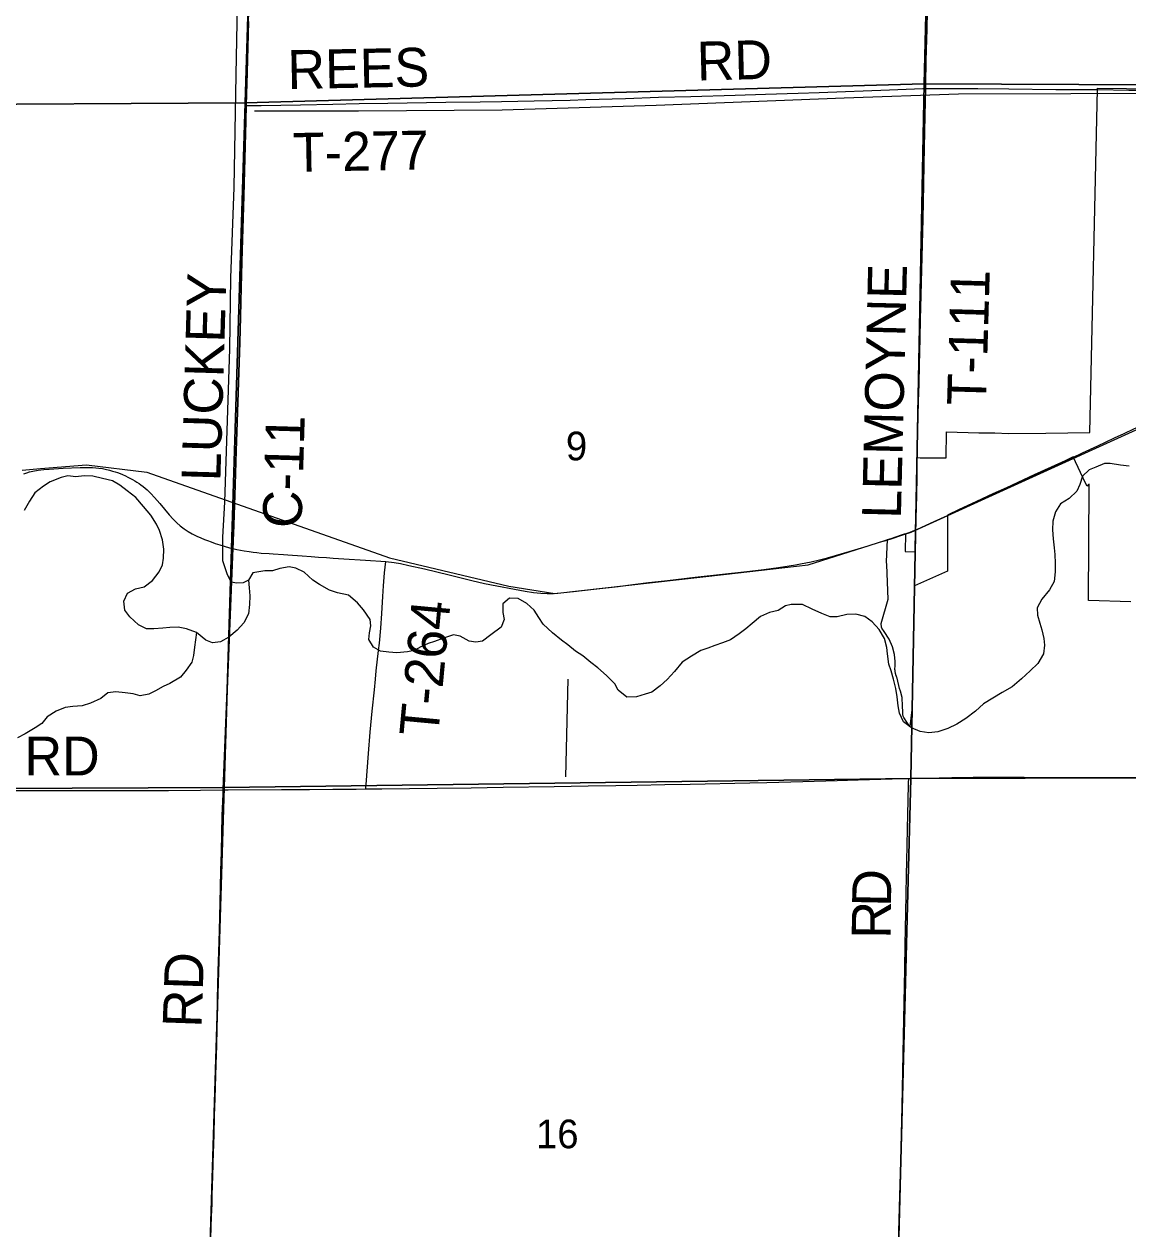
# Model space of a CAD drawing. Extents: x -8.3 to 42.1, y 0 to 22.
# Drawn here: x 3.551 to 5.164, y 15.682 to 17.442 of the extents above; entities that cross this region are included whole.
import ezdxf

# ---------------------------------------------------------------- set-up
doc = ezdxf.new("R2010")
doc.units = 0
for name, color, linetype in [('GM_X_Corporation', 7, 'Continuous'), ('GM_X_County_Road', 7, 'Continuous'), ('GM_X_County_Road_Text', 7, 'Continuous'), ('GM_X_Major_River', 7, 'Continuous'), ('GM_X_Minor_River', 7, 'Continuous'), ('GM_X_Rail_Line', 7, 'Continuous'), ('GM_X_Section', 7, 'Continuous'), ('GM_X_Section_Text', 7, 'Continuous'), ('GM_X_State_Route', 7, 'Continuous'), ('GM_X_Township_Road', 7, 'Continuous'), ('GM_X_Township_Road_Text', 7, 'Continuous')]:
    doc.layers.add(name, color=color, linetype=linetype)

msp = doc.modelspace()

# ---------------------------------------------------------------- linework, layer by layer
at = {"layer": 'GM_X_Corporation'}
msp.add_lwpolyline([(5.168, 16.5978), (5.1062, 16.5996), (5.1071, 16.7676), (5.1071, 16.7697), (5.1065, 16.7694), (5.1063, 16.7691), (5.1056, 16.7685), (5.1047, 16.7672), (5.1043, 16.7669), (5.104, 16.7665), (5.1016, 16.7709), (5.0836, 16.8095), (5.0718, 16.8039), (5.0268, 16.7831), (4.986, 16.7642), (4.9662, 16.7553), (4.9423, 16.7441), (4.917, 16.7324), (4.8999, 16.7245), (4.8999, 16.6423), (4.8518, 16.6212), (4.8486, 16.4449), (4.8481, 16.4398), (4.8451, 16.4155), (4.8406, 16.4218), (4.836, 16.4288), (4.8353, 16.4306), (4.8348, 16.4332), (4.8347, 16.4357), (4.8345, 16.4469), (4.834, 16.4565), (4.8339, 16.4579), (4.8312, 16.4671), (4.8301, 16.4709), (4.8266, 16.4862), (4.8262, 16.487), (4.8254, 16.4888), (4.8247, 16.4909), (4.8245, 16.4917), (4.824, 16.4932), (4.8239, 16.4939), (4.8237, 16.4951), (4.8234, 16.4973), (4.8233, 16.4989), (4.8233, 16.5008), (4.8234, 16.5027), (4.8235, 16.5034), (4.8237, 16.5103), (4.8227, 16.5208), (4.8199, 16.5317), (4.815, 16.543), (4.8073, 16.5541), (4.8042, 16.559), (4.8034, 16.5607), (4.803, 16.5659), (4.8134, 16.6015), (4.8113, 16.6515), (4.8111, 16.656), (4.8125, 16.6887), (4.8175, 16.6904), (4.833, 16.6956), (4.8386, 16.6976), (4.8383, 16.6711), (4.8526, 16.6707), (4.8533, 16.7034), (4.8543, 16.7338), (4.8555, 16.7785), (4.8557, 16.8086), (4.8599, 16.8081), (4.8983, 16.8082), (4.8986, 16.8461), (4.9457, 16.8448), (4.9694, 16.8448), (4.9892, 16.8438), (5.0437, 16.8441), (5.1079, 16.8452), (5.1193, 17.3466), (5.1193, 17.3479), (5.2037, 17.3472)], dxfattribs=at)
at = {"layer": 'GM_X_County_Road'}
for points in [[(3.8757, 17.3226), (3.877, 17.3706), (3.879, 17.4452), (3.8806, 17.5011), (3.8816, 17.5384), (3.8831, 17.5849), (3.8856, 17.6719), (3.8863, 17.7061), (3.8879, 17.7527), (3.8907, 17.849), (3.8925, 17.908), (3.8942, 17.967), (3.8964, 18.0294), (3.8977, 18.0647), (3.9001, 18.1317), (3.9019, 18.1908), (3.9046, 18.2684), (3.9056, 18.2932), (3.9067, 18.3032), (3.9076, 18.314), (3.9079, 18.3179)], [(3.8562, 16.6754), (3.8567, 16.684), (3.8569, 16.6872), (3.8578, 16.7089), (3.8596, 16.7679), (3.861, 16.8176), (3.862, 16.8456), (3.8634, 16.8891), (3.8662, 16.976), (3.8674, 17.0133), (3.8684, 17.0568), (3.8694, 17.0941), (3.8722, 17.1904), (3.8751, 17.2991), (3.8757, 17.3226)]]:
    msp.add_lwpolyline(points, dxfattribs=at)
at = {"layer": 'GM_X_Major_River'}
for points in [[(5.1655, 16.7961), (5.1526, 16.7975), (5.1379, 16.8), (5.1296, 16.8), (5.1166, 16.7946), (5.107, 16.7906), (5.0973, 16.7814), (5.0932, 16.7693), (5.0892, 16.7596), (5.0776, 16.7485), (5.0649, 16.7408), (5.0578, 16.7292), (5.054, 16.7153), (5.0533, 16.7028), (5.0542, 16.6898), (5.0557, 16.6765), (5.0566, 16.667), (5.0571, 16.6541), (5.0575, 16.6415), (5.056, 16.6275), (5.0489, 16.6152), (5.0379, 16.6014), (5.0312, 16.589), (5.0317, 16.5784), (5.0348, 16.5666), (5.0376, 16.557), (5.0407, 16.544), (5.0416, 16.5345), (5.0401, 16.5217), (5.0318, 16.5074), (5.0206, 16.4967), (5.0082, 16.4852), (4.9946, 16.4734), (4.9797, 16.4654), (4.9527, 16.4486), (4.9411, 16.4379), (4.9268, 16.4272), (4.9138, 16.4192), (4.9007, 16.4127), (4.8858, 16.4077), (4.8729, 16.4062), (4.8601, 16.4084), (4.8474, 16.4136), (4.8358, 16.4222), (4.8297, 16.4349), (4.8281, 16.4459), (4.8265, 16.4589)], [(3.8621, 16.5562), (3.8501, 16.5459), (3.8378, 16.5394), (3.8261, 16.5377), (3.8163, 16.5418), (3.803, 16.5531), (3.7883, 16.5582), (3.7759, 16.5606), (3.7638, 16.5601), (3.7539, 16.5592), (3.7406, 16.5584), (3.73, 16.5583), (3.718, 16.5639), (3.7054, 16.5756), (3.6981, 16.5856), (3.6967, 16.5988), (3.7021, 16.6102), (3.714, 16.6167), (3.7262, 16.6195), (3.7386, 16.6287), (3.7483, 16.6413), (3.7531, 16.6515), (3.7549, 16.6613), (3.7552, 16.6746), (3.7533, 16.6883), (3.7487, 16.7017), (3.7444, 16.7113), (3.736, 16.7244), (3.7257, 16.7371), (3.7143, 16.7499), (3.7017, 16.7597), (3.6909, 16.7683), (3.6804, 16.7743), (3.6658, 16.7781), (3.6515, 16.7811), (3.639, 16.7817), (3.6268, 16.7805), (3.6151, 16.7816), (3.6052, 16.7795), (3.5891, 16.7731), (3.5795, 16.7669), (3.5668, 16.7569), (3.5589, 16.7446), (3.551, 16.7311)], [(4.8265, 16.4589), (4.8245, 16.4711), (4.8211, 16.4845), (4.8176, 16.4967), (4.8144, 16.5066), (4.8125, 16.5215), (4.8113, 16.531), (4.8078, 16.544), (4.8002, 16.5574), (4.7898, 16.5683), (4.7794, 16.5762), (4.7663, 16.5799), (4.753, 16.5791), (4.7389, 16.576), (4.7287, 16.5759), (4.7163, 16.5807), (4.7025, 16.5871), (4.6882, 16.5939), (4.6716, 16.5939), (4.6632, 16.5919), (4.6528, 16.5849), (4.6398, 16.5822), (4.6268, 16.5761), (4.6148, 16.5661), (4.6052, 16.558), (4.5955, 16.551), (4.5832, 16.5422), (4.5713, 16.5379), (4.5603, 16.534), (4.5499, 16.5301), (4.5396, 16.5266), (4.5258, 16.5182), (4.5123, 16.5094), (4.501, 16.496), (4.4905, 16.4841), (4.4804, 16.4752), (4.4681, 16.4657), (4.4585, 16.4629), (4.4455, 16.459), (4.4315, 16.4586), (4.4189, 16.4684), (4.4138, 16.478), (4.402, 16.49), (4.3894, 16.5013), (4.379, 16.5092), (4.3671, 16.519), (4.3567, 16.5257), (4.3456, 16.535), (4.3359, 16.5417), (4.3229, 16.5523), (4.3092, 16.5652), (4.303, 16.5748), (4.2961, 16.5856), (4.2857, 16.5953), (4.273, 16.6025), (4.2601, 16.6028), (4.2505, 16.595), (4.2505, 16.5821), (4.2522, 16.5718), (4.2481, 16.5606), (4.2327, 16.5495), (4.2207, 16.54), (4.2112, 16.5387), (4.2014, 16.5404), (4.1883, 16.5476), (4.1782, 16.5497), (4.1637, 16.5448), (4.1507, 16.5398), (4.1411, 16.537), (4.1308, 16.5319), (4.1208, 16.5268), (4.1109, 16.5248), (4.0957, 16.5233), (4.084, 16.5243), (4.0719, 16.5257), (4.0614, 16.5315), (4.0545, 16.5425), (4.0555, 16.5523), (4.0577, 16.5625), (4.0568, 16.572), (4.0469, 16.5859), (4.0381, 16.5964), (4.0251, 16.6073), (4.0089, 16.6107), (3.9974, 16.6149), (3.9827, 16.6228), (3.973, 16.6291), (3.96, 16.6412), (3.9481, 16.6468), (3.9383, 16.6489), (3.9246, 16.6462), (3.9139, 16.643), (3.9025, 16.6429), (3.885, 16.64), (3.8788, 16.6293), (3.8796, 16.618), (3.8808, 16.6066), (3.8801, 16.5937), (3.879, 16.5801), (3.8719, 16.567), (3.8621, 16.5562)]]:
    msp.add_lwpolyline(points, dxfattribs=at)
at = {"layer": 'GM_X_Minor_River'}
for points in [[(3.8788, 16.6293), (3.8711, 16.6256), (3.8618, 16.6248), (3.8536, 16.6266), (3.8475, 16.6386), (3.8412, 16.6577), (3.8413, 16.6922), (3.8444, 16.7434), (3.8481, 16.8625), (3.8518, 16.9671), (3.8529, 17.0711), (3.8581, 17.203), (3.861, 17.3677), (3.8634, 17.4951), (3.8685, 17.624), (3.8727, 17.7484), (3.8761, 17.8546), (3.8811, 18.0272), (3.8862, 18.1546), (3.8894, 18.2972)], [(3.8877, 17.315), (4.0396, 17.3152), (4.2494, 17.3165), (4.4745, 17.3232), (4.749, 17.334), (4.9161, 17.3399), (5.0801, 17.3405), (5.2547, 17.3408)], [(3.803, 16.5531), (3.7998, 16.5315), (3.7987, 16.5194), (3.7962, 16.5096), (3.788, 16.4977), (3.7794, 16.4876), (3.764, 16.4785), (3.7544, 16.4738), (3.7429, 16.4676), (3.7333, 16.4629), (3.7204, 16.4606), (3.7102, 16.4631), (3.6985, 16.4649), (3.6849, 16.466), (3.6735, 16.4648), (3.6631, 16.4563), (3.6482, 16.4498), (3.6359, 16.4456), (3.6223, 16.4448), (3.6109, 16.4435), (3.5979, 16.4378), (3.5848, 16.4297), (3.577, 16.42), (3.5674, 16.4134), (3.5528, 16.4047), (3.5413, 16.3989)], [(4.3455, 16.4846), (4.3419, 16.342)]]:
    msp.add_lwpolyline(points, dxfattribs=at)
at = {"layer": 'GM_X_Rail_Line'}
msp.add_lwpolyline([(3.5481, 16.7901), (3.5751, 16.7924), (3.642, 16.7979), (3.7302, 16.7871), (4.0849, 16.6622), (4.2594, 16.6204), (4.3265, 16.61), (4.5771, 16.6383), (4.6964, 16.6517), (4.847, 16.6995), (5.3428, 16.9248)], dxfattribs=at)
at = {"layer": 'GM_X_Section'}
for points in [[(2.9069, 18.3295), (2.9164, 18.3298), (3.9047, 18.3241), (3.8739, 17.3266), (2.8735, 17.321)], [(3.9115, 18.3241), (4.8893, 18.3249), (4.866, 17.3546), (3.8739, 17.3266), (3.9047, 18.3241)], [(4.9147, 18.3251), (5.8932, 18.3221), (5.8682, 17.3386), (5.431, 17.3522), (4.866, 17.3546), (4.8893, 18.3249)], [(4.866, 17.3546), (4.8464, 16.3395), (3.8435, 16.3264), (3.8739, 17.3266)], [(5.8682, 17.3386), (5.8503, 16.3424), (4.8464, 16.3395), (4.866, 17.3546), (5.431, 17.3522)], [(3.8739, 17.3266), (3.8435, 16.3264), (2.8424, 16.322), (2.8735, 17.321)], [(3.8435, 16.3264), (4.8464, 16.3395), (4.8204, 15.3344), (3.8127, 15.327)], [(4.8464, 16.3395), (5.8503, 16.3424), (5.8197, 15.3608), (4.8204, 15.3344)], [(3.8435, 16.3264), (3.8127, 15.327), (2.8124, 15.3208), (2.8424, 16.322)]]:
    msp.add_lwpolyline(points, close=True, dxfattribs=at)
at = {"layer": 'GM_X_State_Route'}
msp.add_line((5.0839, 16.809), (5.0953, 16.8145), dxfattribs=at)
for points in [[(5.1589, 16.8442), (5.1715, 16.8501), (5.1828, 16.8552), (5.2025, 16.8642), (5.2209, 16.8722), (5.2228, 16.873), (5.2326, 16.8773), (5.2531, 16.8864), (5.2686, 16.8933), (5.2769, 16.8974), (5.284, 16.9005), (5.2872, 16.902), (5.2956, 16.9059), (5.3006, 16.908), (5.3091, 16.9116), (5.3176, 16.9154), (5.3316, 16.9218), (5.3356, 16.9237), (5.3499, 16.9301), (5.3519, 16.931)], [(5.0953, 16.8145), (5.0971, 16.8154), (5.1197, 16.8258), (5.1438, 16.8372), (5.158, 16.8438), (5.1589, 16.8442)], [(3.5507, 16.7847), (3.5552, 16.7863), (3.5591, 16.7874), (3.564, 16.7885), (3.5714, 16.7899), (3.5801, 16.7911), (3.5875, 16.7917), (3.608, 16.7928), (3.6329, 16.7937), (3.6429, 16.7939), (3.651, 16.7939), (3.6556, 16.7936), (3.6604, 16.7931), (3.6654, 16.7923), (3.6696, 16.7914), (3.6757, 16.7901), (3.6802, 16.7888), (3.6841, 16.7875), (3.6875, 16.7864), (3.6912, 16.785), (3.695, 16.7835), (3.6991, 16.7817), (3.7028, 16.7799), (3.7065, 16.778), (3.7096, 16.7763), (3.7126, 16.7746), (3.7158, 16.7726), (3.7189, 16.7705), (3.7218, 16.7684), (3.7249, 16.7661), (3.7278, 16.7638), (3.7307, 16.7612), (3.7361, 16.756), (3.7417, 16.7501), (3.7493, 16.7411), (3.763, 16.7249), (3.7688, 16.7185), (3.7718, 16.7155), (3.774, 16.7133), (3.779, 16.7088), (3.785, 16.7041), (3.7905, 16.7005), (3.7968, 16.6968), (3.8033, 16.6937), (3.8093, 16.691), (3.8146, 16.6888), (3.8192, 16.6871), (3.8241, 16.6853), (3.8303, 16.683), (3.8369, 16.6808), (3.8433, 16.6788), (3.8513, 16.6766), (3.8562, 16.6754)], [(4.9001, 16.724), (4.9172, 16.7319), (4.9426, 16.7435), (4.9664, 16.7548), (4.9862, 16.7636), (5.027, 16.7825), (5.072, 16.8034), (5.0839, 16.809)], [(4.8535, 16.7028), (4.8561, 16.7038), (4.8807, 16.7149), (4.8955, 16.7217), (4.9001, 16.724)], [(3.8562, 16.6754), (3.8616, 16.6742), (3.8671, 16.6731), (3.8725, 16.6721), (3.8799, 16.671), (3.8855, 16.6703), (3.8912, 16.6696), (3.8973, 16.669), (3.9089, 16.6681), (3.9151, 16.6676), (3.9299, 16.6666), (3.9361, 16.6662), (3.9572, 16.6647), (3.9704, 16.6638), (3.9809, 16.663), (3.9927, 16.6623), (4.0025, 16.6617), (4.018, 16.6606), (4.0496, 16.6587), (4.0794, 16.6564), (4.0915, 16.655), (4.1008, 16.6535), (4.113, 16.651), (4.1358, 16.6457), (4.1539, 16.6415), (4.1721, 16.6371), (4.2052, 16.6288), (4.2234, 16.6246), (4.2416, 16.6209), (4.2676, 16.616), (4.2829, 16.6133), (4.2952, 16.6115), (4.3059, 16.6103), (4.3152, 16.6099), (4.3245, 16.61), (4.3353, 16.6108), (4.3538, 16.6127), (4.3878, 16.6166), (4.4187, 16.6203), (4.4402, 16.623), (4.4634, 16.6259), (4.4912, 16.629), (4.5314, 16.6335), (4.6071, 16.6422), (4.6318, 16.6451), (4.6533, 16.648), (4.6778, 16.6519), (4.6855, 16.6532), (4.7007, 16.6561), (4.7128, 16.6588), (4.7248, 16.6619), (4.7562, 16.671), (4.7829, 16.6792), (4.8023, 16.6851), (4.8118, 16.6879)], [(4.8118, 16.6879), (4.8127, 16.6881), (4.8178, 16.6898), (4.8333, 16.695), (4.8388, 16.697)], [(4.8388, 16.697), (4.8478, 16.7005), (4.8535, 16.7028)]]:
    msp.add_lwpolyline(points, dxfattribs=at)
at = {"layer": 'GM_X_Township_Road'}
for points in [[(4.8682, 17.3477), (4.8683, 17.3535), (4.869, 17.3883), (4.8703, 17.4343), (4.8714, 17.4877), (4.8721, 17.5219), (4.8731, 17.5692), (4.8737, 17.6152), (4.8744, 17.6456), (4.8751, 17.6711), (4.8763, 17.7283), (4.8771, 17.7637), (4.8792, 17.8626), (4.8799, 17.8918), (4.8811, 17.9272), (4.8824, 17.9869), (4.8834, 18.0391), (4.8844, 18.105), (4.8861, 18.1864), (4.8867, 18.2156), (4.8879, 18.2678), (4.8884, 18.3026), (4.8885, 18.3129)], [(3.8788, 17.4457), (3.8768, 17.3711), (3.8755, 17.3232), (3.8748, 17.2997), (3.8719, 17.191), (3.8692, 17.0947), (3.8682, 17.0574), (3.8672, 17.0139), (3.866, 16.9766), (3.8632, 16.8896), (3.8617, 16.8461), (3.8608, 16.8182), (3.8594, 16.7685), (3.8576, 16.7095), (3.8566, 16.6877), (3.8565, 16.6846), (3.856, 16.676), (3.8419, 16.3235), (3.8417, 16.3165), (3.8406, 16.2854), (3.8394, 16.2325), (3.8386, 16.2045), (3.8373, 16.1579), (3.8364, 16.1175), (3.836, 16.1019), (3.8355, 16.0864), (3.8347, 16.058), (3.8337, 16.0179), (3.8335, 16.0053), (3.8332, 15.9933), (3.8326, 15.9745), (3.832, 15.9496), (3.8311, 15.9217), (3.8296, 15.8719), (3.8287, 15.847), (3.828, 15.819), (3.8269, 15.7786), (3.8262, 15.7568), (3.826, 15.7474), (3.8254, 15.7288), (3.8252, 15.7195), (3.8247, 15.7073), (3.8245, 15.7014), (3.8238, 15.683), (3.8224, 15.6394)], [(3.8224, 15.6394), (3.8238, 15.683), (3.8245, 15.7014), (3.8247, 15.7073), (3.8252, 15.7195), (3.8254, 15.7288), (3.826, 15.7474), (3.8262, 15.7568), (3.8269, 15.7786), (3.828, 15.819), (3.8287, 15.847), (3.8296, 15.8719), (3.8311, 15.9217), (3.832, 15.9496), (3.8326, 15.9745), (3.8332, 15.9933), (3.8335, 16.0053), (3.8337, 16.0179), (3.8347, 16.058), (3.8355, 16.0864), (3.836, 16.1019), (3.8364, 16.1175), (3.8373, 16.1579), (3.8386, 16.2045), (3.8394, 16.2325), (3.8406, 16.2854), (3.8417, 16.3165), (3.8419, 16.3235), (3.856, 16.676), (3.8565, 16.6846), (3.8566, 16.6877), (3.8576, 16.7095), (3.8594, 16.7685), (3.8608, 16.8182), (3.8617, 16.8461), (3.8632, 16.8896), (3.866, 16.9766), (3.8672, 17.0139), (3.8682, 17.0574), (3.8692, 17.0947), (3.8719, 17.191), (3.8748, 17.2997), (3.8755, 17.3232), (3.8768, 17.3711), (3.8788, 17.4457)], [(3.8757, 17.3226), (3.8973, 17.323), (3.9548, 17.3239), (4.002, 17.3248), (4.0404, 17.3256), (4.0824, 17.3264), (4.1669, 17.3276), (4.2174, 17.3283), (4.2485, 17.3288), (4.2962, 17.3296), (4.3488, 17.3308), (4.3718, 17.3316), (4.4295, 17.3332), (4.478, 17.3349), (4.5249, 17.336), (4.5898, 17.3378), (4.6341, 17.3391), (4.6819, 17.3408), (4.7124, 17.3416), (4.8152, 17.3457), (4.8639, 17.3475), (4.8682, 17.3477)], [(4.8559, 16.8081), (4.8563, 16.8271), (4.8566, 16.8482), (4.8577, 16.8905), (4.8584, 16.916), (4.859, 16.9433), (4.86, 16.9825), (4.8608, 17.011), (4.8613, 17.0272), (4.8644, 17.1565), (4.8654, 17.2074), (4.8659, 17.2373), (4.8675, 17.3081), (4.8682, 17.3477)], [(4.8682, 17.3477), (4.8869, 17.3478), (4.9133, 17.3476), (4.9445, 17.3474), (4.9897, 17.3469), (5.0582, 17.3464), (5.08, 17.3462), (5.1171, 17.346), (5.1195, 17.346)], [(5.1195, 17.346), (5.165, 17.3454), (5.1882, 17.3451), (5.2031, 17.345), (5.2091, 17.345), (5.2219, 17.3448)], [(4.8535, 16.7028), (4.8546, 16.7333), (4.8557, 16.778), (4.8559, 16.8081)], [(4.0688, 16.5265), (4.07, 16.5374), (4.072, 16.5591), (4.0736, 16.5808), (4.0752, 16.6057), (4.0762, 16.6213), (4.0776, 16.64), (4.0794, 16.6564)], [(4.0502, 16.3244), (4.0504, 16.3275), (4.0506, 16.331), (4.054, 16.376), (4.0565, 16.4071), (4.0595, 16.4381), (4.0628, 16.4691), (4.0644, 16.4847), (4.0656, 16.4971), (4.0688, 16.5265)], [(4.0502, 16.3244), (4.0547, 16.3244), (4.0736, 16.3246), (4.1544, 16.3253), (4.2041, 16.3261), (4.2508, 16.3268), (4.3253, 16.3279), (4.3751, 16.3288), (4.4155, 16.3292), (4.4465, 16.3297), (4.4869, 16.3306), (4.5242, 16.3314), (4.6112, 16.3332), (4.6361, 16.3337), (4.6889, 16.3352), (4.7386, 16.3367), (4.7697, 16.3375), (4.8194, 16.3391), (4.8411, 16.3395), (4.8434, 16.3396)], [(4.8231, 15.3353), (4.8234, 15.3475), (4.8243, 15.4034), (4.8248, 15.4361), (4.826, 15.5263), (4.8273, 15.6102), (4.8281, 15.6429), (4.8305, 15.73), (4.8318, 15.7797), (4.8336, 15.8605), (4.8358, 15.9631), (4.8376, 16.0611), (4.8383, 16.0969), (4.8391, 16.1435), (4.8402, 16.1979), (4.8407, 16.2197), (4.8412, 16.2414), (4.8416, 16.2663), (4.8421, 16.2865), (4.8424, 16.3083), (4.8431, 16.3301), (4.8432, 16.3332), (4.8434, 16.3396)], [(4.8434, 16.3396), (4.866, 16.34), (4.8877, 16.3404), (4.9064, 16.3409), (4.9374, 16.3415), (4.9591, 16.3416), (5.012, 16.3415), (5.0773, 16.3412), (5.1239, 16.3411), (5.1643, 16.3411), (5.1891, 16.3412), (5.2575, 16.3414), (5.3443, 16.3415)], [(3.529, 16.322), (3.5756, 16.3219), (3.6191, 16.3219), (3.7093, 16.3221), (3.7621, 16.3222), (3.8087, 16.3225), (3.8422, 16.3229)], [(3.8226, 15.6389), (3.824, 15.6824), (3.8247, 15.7008), (3.8249, 15.7067), (3.8254, 15.7189), (3.8256, 15.7282), (3.8262, 15.7469), (3.8265, 15.7562), (3.8271, 15.778), (3.8283, 15.8184), (3.829, 15.8464), (3.8298, 15.8713), (3.8313, 15.9211), (3.8322, 15.9491), (3.8329, 15.974), (3.8335, 15.9927), (3.8337, 16.0047), (3.8339, 16.0173), (3.8349, 16.0574), (3.8357, 16.0858), (3.8362, 16.1014), (3.8366, 16.1169), (3.8376, 16.1573), (3.8389, 16.2039), (3.8397, 16.2319), (3.8408, 16.2849), (3.8419, 16.316), (3.8422, 16.3229)], [(3.8422, 16.3229), (3.8491, 16.323), (3.9273, 16.3236), (3.9679, 16.3236), (4.0021, 16.3241), (4.0363, 16.3242), (4.0502, 16.3244)]]:
    msp.add_lwpolyline(points, dxfattribs=at)

# ---------------------------------------------------------------- texts
at = {"layer": 'GM_X_County_Road_Text'}
for s, rotation, p in [('LUCKEY', 88.3106, (3.8377, 16.7733)), ('C-11', 88.2741, (3.9562, 16.7049))]:
    msp.add_text(s, height=0.05682, rotation=rotation, dxfattribs=at).set_placement(p)
at = {"layer": 'GM_X_Section_Text'}
for s, height, p in [('9', 0.0419, (4.3425, 16.8044)), ('16', 0.04186, (4.2988, 15.7994))]:
    msp.add_text(s, height=height, rotation=0, dxfattribs=at).set_placement(p)
at = {"layer": 'GM_X_Township_Road_Text'}
for s, height, rotation, p in [('REES', 0.05682, 1.1238, (3.9364, 17.3467)), ('RD', 0.05682, 1.4825, (4.5345, 17.3591)), ('T-277', 0.05682, 1.1131, (3.9443, 17.2257)), ('LEMOYNE', 0.05682, 88.6029, (4.8319, 16.7187)), ('T-111', 0.05682, 88.3311, (4.9561, 16.8839)), ('T-264', 0.05682, 84.6793, (4.1557, 16.3993)), ('RD', 0.05682, 0, (3.5517, 16.344)), ('D', 0.0568, 88.816, (4.8173, 16.1518)), ('R', 0.0568, 89.4809, (4.8169, 16.1054)), ('RD', 0.05682, 88.0242, (3.8102, 15.9751))]:
    msp.add_text(s, height=height, rotation=rotation, dxfattribs=at).set_placement(p)

doc.saveas('drawing.dxf')
